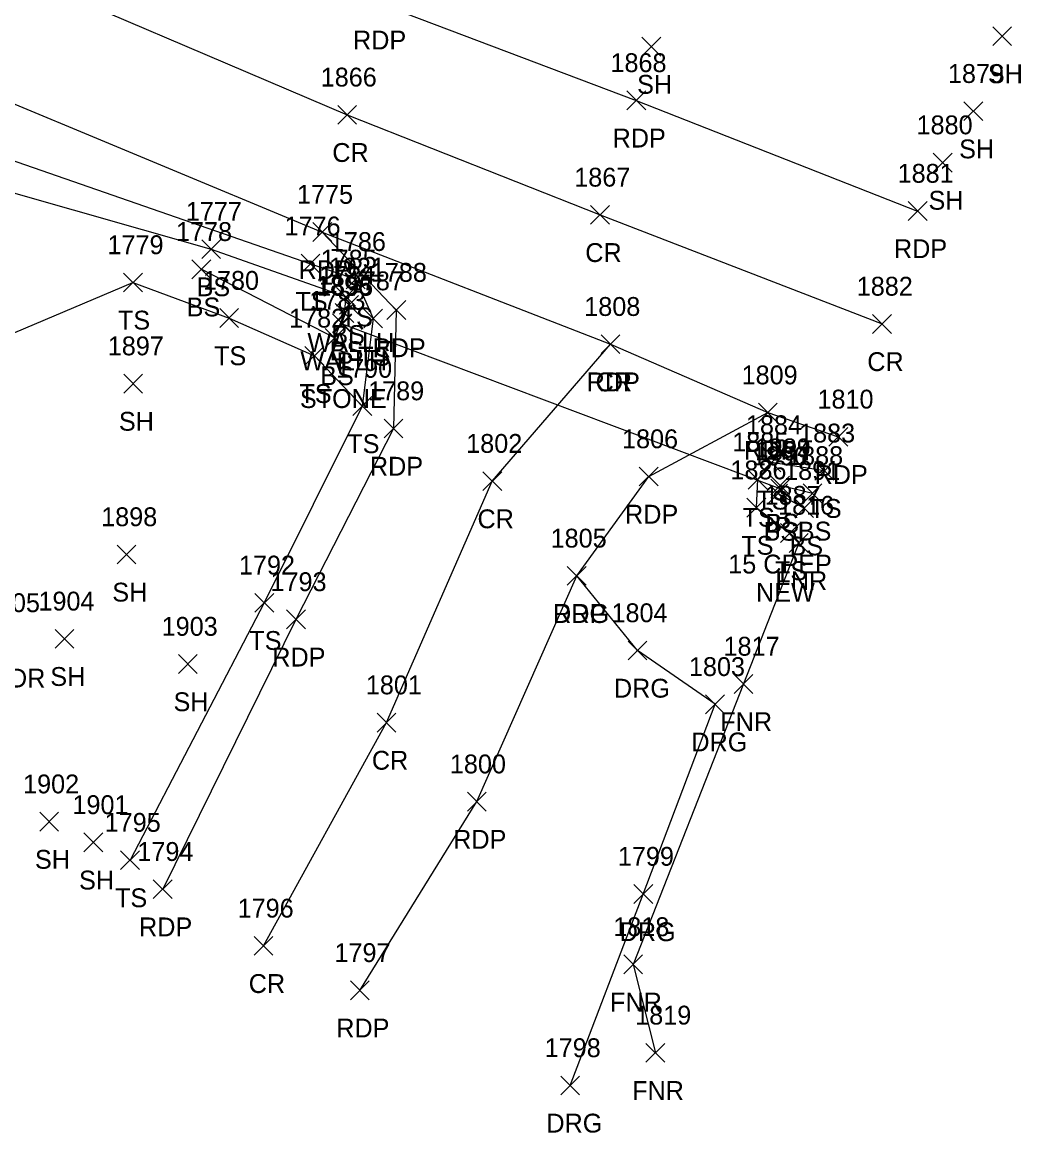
# Model space of a CAD drawing. Extents: x 1586965 to 1590952, y 716317 to 720029.
# Drawn here: x 1588133.2 to 1588239.2, y 719561.4 to 719679.3 of the extents above; entities that cross this region are included whole.
import ezdxf

# ---------------------------------------------------------------- set-up
doc = ezdxf.new("R2010")
doc.units = 0
for name, color, linetype in [('D_A', 7, 'Continuous'), ('D_C', 7, 'Continuous'), ('D_I', 7, 'Continuous'), ('D_TIC', 7, 'Continuous'), ('DCP', 7, 'Continuous'), ('DHW', 7, 'Continuous'), ('L_A', 7, 'Continuous'), ('L_I', 7, 'Continuous'), ('L_TIC', 7, 'Continuous'), ('LELB', 7, 'Continuous'), ('LFNC', 7, 'Continuous'), ('P_A', 7, 'Continuous'), ('P_I', 7, 'Continuous'), ('P_TIC', 7, 'Continuous'), ('PET', 7, 'Continuous'), ('PRC', 7, 'Continuous'), ('R_A', 7, 'Continuous'), ('R_I', 7, 'Continuous'), ('R_TIC', 7, 'Continuous'), ('RDG', 7, 'Continuous')]:
    doc.layers.add(name, color=color, linetype=linetype)

msp = doc.modelspace()

# ---------------------------------------------------------------- linework, layer by layer
at = {"layer": 'D_TIC'}
for points in [[(1588166.93, 719648.29), (1588168.93, 719650.29)], [(1588168.93, 719648.29), (1588166.93, 719650.29)], [(1588166.18, 719646.35), (1588168.18, 719648.35)], [(1588168.18, 719646.35), (1588166.18, 719648.35)], [(1588166.24, 719646.26), (1588168.24, 719648.26)], [(1588168.24, 719646.26), (1588166.24, 719648.26)], [(1588212.71, 719628.79), (1588214.71, 719630.79)], [(1588214.71, 719628.79), (1588212.71, 719630.79)]]:
    msp.add_lwpolyline(points, dxfattribs=at)
at = {"layer": 'DCP'}
msp.add_lwpolyline([(1588213.71, 719629.79), (1588167.24, 719647.26)], dxfattribs=at)
at = {"layer": 'DHW'}
msp.add_lwpolyline([(1588167.18, 719647.35), (1588167.93, 719649.29)], dxfattribs=at)
at = {"layer": 'L_TIC'}
for points in [[(1588236.25, 719676.81), (1588238.25, 719678.81)], [(1588238.25, 719676.81), (1588236.25, 719678.81)], [(1588199.02, 719675.69), (1588201.02, 719677.69)], [(1588201.02, 719675.69), (1588199.02, 719677.69)], [(1588233.2, 719668.84), (1588235.2, 719670.84)], [(1588235.2, 719668.84), (1588233.2, 719670.84)], [(1588229.95, 719663.39), (1588231.95, 719665.39)], [(1588231.95, 719663.39), (1588229.95, 719665.39)], [(1588152.31, 719654.21), (1588154.31, 719656.21)], [(1588154.31, 719654.21), (1588152.31, 719656.21)], [(1588162.84, 719652.66), (1588164.84, 719654.66)], [(1588164.84, 719652.66), (1588162.84, 719654.66)], [(1588151.26, 719652.07), (1588153.26, 719654.07)], [(1588153.26, 719652.07), (1588151.26, 719654.07)], [(1588144, 719650.67), (1588146, 719652.67)], [(1588146, 719650.67), (1588144, 719652.67)], [(1588167.64, 719651.01), (1588169.64, 719653.01)], [(1588169.64, 719651.01), (1588167.64, 719653.01)], [(1588166.62, 719649.14), (1588168.62, 719651.14)], [(1588168.62, 719649.14), (1588166.62, 719651.14)], [(1588166.62, 719649.14), (1588168.62, 719651.14)], [(1588168.62, 719649.14), (1588166.62, 719651.14)], [(1588154.21, 719646.89), (1588156.21, 719648.89)], [(1588156.21, 719646.89), (1588154.21, 719648.89)], [(1588166.45, 719647.42), (1588168.45, 719649.42)], [(1588168.45, 719647.42), (1588166.45, 719649.42)], [(1588169.5, 719646.84), (1588171.5, 719648.84)], [(1588171.5, 719646.84), (1588169.5, 719648.84)], [(1588165.42, 719644.78), (1588167.42, 719646.78)], [(1588167.42, 719644.78), (1588165.42, 719646.78)], [(1588163.26, 719642.88), (1588165.26, 719644.88)], [(1588165.26, 719642.88), (1588163.26, 719644.88)], [(1588144.02, 719639.94), (1588146.02, 719641.94)], [(1588146.02, 719639.94), (1588144.02, 719641.94)], [(1588168.34, 719637.56), (1588170.34, 719639.56)], [(1588170.34, 719637.56), (1588168.34, 719639.56)], [(1588168.34, 719637.56), (1588170.34, 719639.56)], [(1588170.34, 719637.56), (1588168.34, 719639.56)], [(1588211.76, 719631.57), (1588213.76, 719633.57)], [(1588213.76, 719631.57), (1588211.76, 719633.57)], [(1588217.39, 719630.69), (1588219.39, 719632.69)], [(1588219.39, 719630.69), (1588217.39, 719632.69)], [(1588210.3, 719629.75), (1588212.3, 719631.75)], [(1588212.3, 719629.75), (1588210.3, 719631.75)], [(1588212.69, 719629.12), (1588214.69, 719631.12)], [(1588214.69, 719629.12), (1588212.69, 719631.12)], [(1588212.48, 719628.27), (1588214.48, 719630.27)], [(1588214.48, 719628.27), (1588212.48, 719630.27)], [(1588216.12, 719628.29), (1588218.12, 719630.29)], [(1588218.12, 719628.29), (1588216.12, 719630.29)], [(1588210.16, 719626.78), (1588212.16, 719628.78)], [(1588212.16, 719626.78), (1588210.16, 719628.78)], [(1588215.24, 719626.72), (1588217.24, 719628.72)], [(1588217.24, 719626.72), (1588215.24, 719628.72)], [(1588213.73, 719624.08), (1588215.73, 719626.08)], [(1588215.73, 719624.08), (1588213.73, 719626.08)], [(1588214.66, 719623.03), (1588216.66, 719625.03)], [(1588216.66, 719623.03), (1588214.66, 719625.03)], [(1588143.32, 719621.81), (1588145.32, 719623.81)], [(1588145.32, 719621.81), (1588143.32, 719623.81)], [(1588157.94, 719616.68), (1588159.94, 719618.68)], [(1588159.94, 719616.68), (1588157.94, 719618.68)], [(1588136.74, 719612.86), (1588138.74, 719614.86)], [(1588138.74, 719612.86), (1588136.74, 719614.86)], [(1588149.82, 719610.18), (1588151.82, 719612.18)], [(1588151.82, 719610.18), (1588149.82, 719612.18)], [(1588208.81, 719608.07), (1588210.81, 719610.07)], [(1588210.81, 719608.07), (1588208.81, 719610.07)], [(1588135.11, 719593.46), (1588137.11, 719595.46)], [(1588137.11, 719593.46), (1588135.11, 719595.46)], [(1588139.79, 719591.26), (1588141.79, 719593.26)], [(1588141.79, 719591.26), (1588139.79, 719593.26)], [(1588143.69, 719589.38), (1588145.69, 719591.38)], [(1588145.69, 719589.38), (1588143.69, 719591.38)], [(1588197.1, 719578.31), (1588199.1, 719580.31)], [(1588199.1, 719578.31), (1588197.1, 719580.31)], [(1588199.45, 719568.93), (1588201.45, 719570.93)], [(1588201.45, 719568.93), (1588199.45, 719570.93)]]:
    msp.add_lwpolyline(points, dxfattribs=at)
at = {"layer": 'LELB'}
for points in [[(1587769.54, 719828.25), (1587817.81, 719818.92), (1587845.39, 719810.87), (1587866.59, 719802.16), (1587894.5, 719791.41), (1587924.64, 719774.45), (1587960.66, 719756.07), (1587994.24, 719738.05), (1588029.81, 719715.93), (1588049.13, 719705.79), (1588061.35, 719699.86), (1588090.7, 719682.25), (1588125.12, 719667.08), (1588163.84, 719653.66), (1588168.64, 719652.01), (1588170.5, 719647.84), (1588169.34, 719638.56), (1588158.94, 719617.68), (1588144.69, 719590.38)], [(1587769.54, 719828.25), (1587817.81, 719818.92), (1587845.39, 719810.87), (1587866.59, 719802.16), (1587894.5, 719791.41), (1587924.64, 719774.45), (1587960.66, 719756.07), (1587994.24, 719738.05), (1588029.81, 719715.93), (1588049.13, 719705.79), (1588061.35, 719699.86), (1588090.7, 719682.25), (1588125.12, 719667.08), (1588163.84, 719653.66), (1588168.64, 719652.01), (1588170.5, 719647.84), (1588169.34, 719638.56), (1588158.94, 719617.68), (1588144.69, 719590.38)], [(1587893.61, 719788.22), (1587923.32, 719772.46), (1587959.45, 719753.99), (1587990.31, 719736.86), (1587992.49, 719736.59), (1587993.47, 719735.49), (1587996.7, 719733.15), (1588001.37, 719729.89), (1588028.07, 719713.52), (1588047.21, 719701.72), (1588059.27, 719695.66), (1588101.54, 719672.79), (1588123.97, 719663.55), (1588153.31, 719655.21), (1588167.62, 719650.14)], [(1587893.61, 719788.22), (1587923.32, 719772.46), (1587959.45, 719753.99), (1587990.31, 719736.86), (1587992.49, 719736.59), (1587993.47, 719735.49), (1587996.7, 719733.15), (1588001.37, 719729.89), (1588028.07, 719713.52), (1588047.21, 719701.72), (1588059.27, 719695.66), (1588101.54, 719672.79), (1588123.97, 719663.55), (1588153.31, 719655.21), (1588167.62, 719650.14)], [(1588058.86, 719666.98), (1588078.17, 719656.22), (1588092.4, 719646.28), (1588110.25, 719653.63), (1588128.24, 719644.6), (1588145, 719651.67), (1588155.21, 719647.89), (1588164.26, 719643.88), (1588169.34, 719638.56)], [(1588058.86, 719666.98), (1588078.17, 719656.22), (1588092.4, 719646.28), (1588110.25, 719653.63), (1588128.24, 719644.6), (1588145, 719651.67), (1588155.21, 719647.89), (1588164.26, 719643.88), (1588169.34, 719638.56)], [(1588152.26, 719653.07), (1588166.42, 719645.78), (1588167.45, 719648.42), (1588167.62, 719650.14)], [(1588152.26, 719653.07), (1588166.42, 719645.78), (1588167.45, 719648.42), (1588167.62, 719650.14)], [(1588218.39, 719631.69), (1588212.76, 719632.57), (1588211.3, 719630.75), (1588211.16, 719627.78), (1588214.73, 719625.08)], [(1588218.39, 719631.69), (1588212.76, 719632.57), (1588211.3, 719630.75), (1588211.16, 719627.78), (1588214.73, 719625.08)], [(1588217.12, 719629.29), (1588213.69, 719630.12), (1588213.48, 719629.27), (1588216.24, 719627.72)], [(1588217.12, 719629.29), (1588213.69, 719630.12), (1588213.48, 719629.27), (1588216.24, 719627.72)]]:
    msp.add_lwpolyline(points, dxfattribs=at)
at = {"layer": 'LFNC'}
msp.add_lwpolyline([(1588215.66, 719624.03), (1588209.81, 719609.07), (1588198.1, 719579.31), (1588200.45, 719569.93)], dxfattribs=at)
at = {"layer": 'P_TIC'}
for points in [[(1588197.42, 719669.99), (1588199.42, 719671.99)], [(1588199.42, 719669.99), (1588197.42, 719671.99)], [(1588166.73, 719668.46), (1588168.73, 719670.46)], [(1588168.73, 719668.46), (1588166.73, 719670.46)], [(1588193.58, 719657.84), (1588195.58, 719659.84)], [(1588195.58, 719657.84), (1588193.58, 719659.84)], [(1588227.28, 719658.25), (1588229.28, 719660.25)], [(1588229.28, 719658.25), (1588227.28, 719660.25)], [(1588164.1, 719656.02), (1588166.1, 719658.02)], [(1588166.1, 719656.02), (1588164.1, 719658.02)], [(1588164.1, 719656.02), (1588166.1, 719658.02)], [(1588166.1, 719656.02), (1588164.1, 719658.02)], [(1588171.95, 719647.74), (1588173.95, 719649.74)], [(1588173.95, 719647.74), (1588171.95, 719649.74)], [(1588223.51, 719646.27), (1588225.51, 719648.27)], [(1588225.51, 719646.27), (1588223.51, 719648.27)], [(1588194.68, 719644.12), (1588196.68, 719646.12)], [(1588196.68, 719644.12), (1588194.68, 719646.12)], [(1588194.68, 719644.12), (1588196.68, 719646.12)], [(1588196.68, 719644.12), (1588194.68, 719646.12)], [(1588211.38, 719636.86), (1588213.38, 719638.86)], [(1588213.38, 719636.86), (1588211.38, 719638.86)], [(1588211.38, 719636.86), (1588213.38, 719638.86)], [(1588213.38, 719636.86), (1588211.38, 719638.86)], [(1588171.66, 719635.17), (1588173.66, 719637.17)], [(1588173.66, 719635.17), (1588171.66, 719637.17)], [(1588218.86, 719634.29), (1588220.86, 719636.29)], [(1588220.86, 719634.29), (1588218.86, 719636.29)], [(1588182.14, 719629.59), (1588184.14, 719631.59)], [(1588184.14, 719629.59), (1588182.14, 719631.59)], [(1588198.74, 719630.08), (1588200.74, 719632.08)], [(1588200.74, 719630.08), (1588198.74, 719632.08)], [(1588191.1, 719619.54), (1588193.1, 719621.54)], [(1588193.1, 719619.54), (1588191.1, 719621.54)], [(1588161.3, 719614.92), (1588163.3, 719616.92)], [(1588163.3, 719614.92), (1588161.3, 719616.92)], [(1588170.92, 719603.97), (1588172.92, 719605.97)], [(1588172.92, 719603.97), (1588170.92, 719605.97)], [(1588180.5, 719595.58), (1588182.5, 719597.58)], [(1588182.5, 719595.58), (1588180.5, 719597.58)], [(1588147.16, 719586.29), (1588149.16, 719588.29)], [(1588149.16, 719586.29), (1588147.16, 719588.29)], [(1588157.86, 719580.28), (1588159.86, 719582.28)], [(1588159.86, 719580.28), (1588157.86, 719582.28)], [(1588168.09, 719575.56), (1588170.09, 719577.56)], [(1588170.09, 719575.56), (1588168.09, 719577.56)]]:
    msp.add_lwpolyline(points, dxfattribs=at)
at = {"layer": 'PET'}
for points in [[(1587795.98, 719858.74), (1587820.3, 719853.13), (1587857.37, 719841.42), (1587877.69, 719833.83), (1587907.04, 719819.84), (1587939.32, 719802.03), (1587973.69, 719783.16), (1588008.21, 719763.34), (1588019.61, 719757.58), (1588045.18, 719744.38), (1588072.84, 719731.02), (1588081.8, 719723.85), (1588104.43, 719712.22), (1588133.68, 719697.26), (1588170.87, 719681.39), (1588198.42, 719670.99), (1588228.28, 719659.25)], [(1587769.59, 719834.05), (1587819.16, 719826.14), (1587848.36, 719816.77), (1587868.73, 719807.9), (1587895.82, 719795.75), (1587926.99, 719779.02), (1587962.24, 719759.15), (1587995.65, 719740.56), (1588031.83, 719719.54), (1588060.89, 719703.68), (1588093.53, 719688.06), (1588127.35, 719672.7), (1588165.1, 719657.02), (1588195.68, 719645.12), (1588212.38, 719637.86), (1588219.86, 719635.29)], [(1588165.1, 719657.02), (1588172.95, 719648.74), (1588172.66, 719636.17), (1588162.3, 719615.92), (1588148.16, 719587.29)], [(1588169.09, 719576.56), (1588181.5, 719596.58), (1588192.1, 719620.54), (1588199.74, 719631.08), (1588212.38, 719637.86)]]:
    msp.add_lwpolyline(points, dxfattribs=at)
at = {"layer": 'PRC'}
for points in [[(1587770.57, 719846.88), (1587822.37, 719838.71), (1587852.49, 719828.95), (1587873.58, 719820.04), (1587901.35, 719807.55), (1587933.49, 719790.19), (1587967.95, 719771.53), (1588001.84, 719751.71), (1588038.72, 719731.7), (1588068.79, 719715.56), (1588099.02, 719700.65), (1588127.2, 719686.75), (1588167.73, 719669.46), (1588194.58, 719658.84), (1588224.51, 719647.27)], [(1587770.57, 719846.88), (1587822.37, 719838.71), (1587852.49, 719828.95), (1587873.58, 719820.04), (1587901.35, 719807.55), (1587933.49, 719790.19), (1587967.95, 719771.53), (1588001.84, 719751.71), (1588038.72, 719731.7), (1588068.79, 719715.56), (1588099.02, 719700.65), (1588127.2, 719686.75), (1588167.73, 719669.46), (1588194.58, 719658.84), (1588224.51, 719647.27)], [(1588158.86, 719581.28), (1588171.92, 719604.97), (1588183.14, 719630.59), (1588195.68, 719645.12)], [(1588158.86, 719581.28), (1588171.92, 719604.97), (1588183.14, 719630.59), (1588195.68, 719645.12)]]:
    msp.add_lwpolyline(points, dxfattribs=at)
at = {"layer": 'R_TIC'}
for points in [[(1588191.1, 719619.54), (1588193.1, 719621.54)], [(1588193.1, 719619.54), (1588191.1, 719621.54)], [(1588197.56, 719611.62), (1588199.56, 719613.62)], [(1588199.56, 719611.62), (1588197.56, 719613.62)], [(1588205.78, 719605.91), (1588207.78, 719607.91)], [(1588207.78, 719605.91), (1588205.78, 719607.91)], [(1588198.17, 719585.78), (1588200.17, 719587.78)], [(1588200.17, 719585.78), (1588198.17, 719587.78)], [(1588190.4, 719565.47), (1588192.4, 719567.47)], [(1588192.4, 719565.47), (1588190.4, 719567.47)]]:
    msp.add_lwpolyline(points, dxfattribs=at)
at = {"layer": 'RDG'}
msp.add_lwpolyline([(1588191.4, 719566.47), (1588199.17, 719586.78), (1588206.78, 719606.91), (1588198.56, 719612.62), (1588192.1, 719620.54)], dxfattribs=at)

# ---------------------------------------------------------------- texts
at = {"layer": 'D_A'}
for s, p in [('WALLH', (1588163.52, 719644.29)), ('WALLH', (1588162.77, 719642.35)), ('P', (1588166.62, 719642.26)), ('P', (1588213.09, 719624.79))]:
    msp.add_text(s, height=2, dxfattribs=at).set_placement(p)
at = {"layer": 'D_C'}
for s, p in [('STONE', (1588162.72, 719638.35)), ('15 CPEP', (1588208.18, 719620.79)), ('NEW', (1588211.13, 719617.79))]:
    msp.add_text(s, height=2, dxfattribs=at).set_placement(p)
at = {"layer": 'D_I'}
for s, p in [('1921', (1588165.8, 719652.29)), ('1896', (1588164.43, 719650.35)), ('1895', (1588164.55, 719650.26)), ('1894', (1588211.02, 719632.79))]:
    msp.add_text(s, height=2, dxfattribs=at).set_placement(p)
at = {"layer": 'L_A'}
for s, p in [('SH', (1588235.74, 719672.81)), ('SH', (1588198.51, 719671.69)), ('SH', (1588232.69, 719664.84)), ('SH', (1588229.44, 719659.39)), ('BS', (1588151.75, 719650.21)), ('BS', (1588150.7, 719648.07)), ('TS', (1588162.25, 719648.66)), ('TS', (1588143.41, 719646.67)), ('TS', (1588167.05, 719647.01)), ('BS', (1588166.06, 719645.14)), ('BS', (1588166.06, 719645.14)), ('BS', (1588165.89, 719643.42)), ('TS', (1588153.61, 719642.89)), ('TS', (1588168.91, 719642.84)), ('BS', (1588164.87, 719640.78)), ('TS', (1588162.67, 719638.88)), ('SH', (1588143.51, 719635.94)), ('TS', (1588167.75, 719633.56)), ('TS', (1588167.75, 719633.56)), ('TS', (1588211.17, 719627.57)), ('TS', (1588216.8, 719626.69)), ('TS', (1588209.71, 719625.75)), ('BS', (1588211.93, 719624.27)), ('BS', (1588212.13, 719625.12)), ('BS', (1588215.56, 719624.29)), ('TS', (1588209.57, 719622.78)), ('BS', (1588214.68, 719622.72)), ('TS', (1588213.14, 719620.08)), ('FNR', (1588213.19, 719619.03)), ('SH', (1588142.81, 719617.81)), ('TS', (1588157.35, 719612.68)), ('WDR', (1588129.32, 719608.69)), ('SH', (1588136.23, 719608.86)), ('SH', (1588149.31, 719606.18)), ('FNR', (1588207.34, 719604.07)), ('SH', (1588134.6, 719589.46)), ('SH', (1588139.28, 719587.26)), ('TS', (1588143.1, 719585.38)), ('FNR', (1588195.64, 719574.31)), ('FNR', (1588197.98, 719564.93))]:
    msp.add_text(s, height=2, dxfattribs=at).set_placement(p)
at = {"layer": 'L_I'}
for s, p in [('1879', (1588231.5, 719672.84)), ('1880', (1588228.17, 719667.39)), ('1777', (1588150.61, 719658.21)), ('1778', (1588149.57, 719656.07)), ('1776', (1588161.09, 719656.66)), ('1786', (1588165.9, 719655.01)), ('1779', (1588142.3, 719654.67)), ('1785', (1588164.92, 719653.14)), ('1785', (1588164.92, 719653.14)), ('1784', (1588164.76, 719651.42)), ('1780', (1588152.43, 719650.89)), ('1787', (1588167.81, 719650.84)), ('1783', (1588163.73, 719648.78)), ('1782', (1588161.57, 719646.88)), ('1897', (1588142.33, 719643.94)), ('1790', (1588166.56, 719641.56)), ('1790', (1588166.56, 719641.56)), ('1884', (1588210.06, 719635.57)), ('1885', (1588208.61, 719633.75)), ('1883', (1588215.7, 719634.69)), ('1889', (1588210.99, 719633.12)), ('1890', (1588210.7, 719632.27)), ('1888', (1588214.43, 719632.29)), ('1886', (1588208.41, 719630.78)), ('1891', (1588214.11, 719630.72)), ('1887', (1588212.04, 719628.08)), ('1816', (1588213.47, 719627.03)), ('1898', (1588141.63, 719625.81)), ('1792', (1588156.25, 719620.68)), ('1905', (1588129.18, 719616.69)), ('1904', (1588134.97, 719616.86)), ('1903', (1588148.05, 719614.18)), ('1817', (1588207.68, 719612.07)), ('1902', (1588133.34, 719597.46)), ('1901', (1588138.58, 719595.26)), ('1795', (1588142, 719593.38)), ('1818', (1588195.98, 719582.31)), ('1819', (1588198.31, 719572.93))]:
    msp.add_text(s, height=2, dxfattribs=at).set_placement(p)
at = {"layer": 'P_A'}
for s, p in [('RDP', (1588168.36, 719676.39)), ('RDP', (1588195.91, 719665.99)), ('CR', (1588166.16, 719664.46)), ('CR', (1588193.01, 719653.84)), ('RDP', (1588225.77, 719654.25)), ('RDP', (1588162.59, 719652.02)), ('RDP', (1588162.59, 719652.02)), ('RDP', (1588170.43, 719643.74)), ('CR', (1588222.94, 719642.27)), ('RDP', (1588193.16, 719640.12)), ('CR', (1588194.11, 719640.12)), ('RDP', (1588209.86, 719632.86)), ('RDP', (1588209.86, 719632.86)), ('RDP', (1588170.15, 719631.17)), ('RDP', (1588217.35, 719630.29)), ('CR', (1588181.57, 719625.59)), ('RDP', (1588197.23, 719626.08)), ('RDP', (1588189.59, 719615.54)), ('RDP', (1588159.79, 719610.92)), ('CR', (1588170.36, 719599.97)), ('RDP', (1588178.99, 719591.58)), ('RDP', (1588145.65, 719582.29)), ('CR', (1588157.29, 719576.28)), ('RDP', (1588166.58, 719571.56))]:
    msp.add_text(s, height=2, dxfattribs=at).set_placement(p)
at = {"layer": 'P_I'}
for s, p in [('1868', (1588195.68, 719673.99)), ('1866', (1588164.93, 719672.46)), ('1881', (1588226.16, 719662.25)), ('1867', (1588191.84, 719661.84)), ('1775', (1588162.41, 719660.02)), ('1775', (1588162.41, 719660.02)), ('1788', (1588170.25, 719651.74)), ('1882', (1588221.82, 719650.27)), ('1808', (1588192.9, 719648.12)), ('1808', (1588192.9, 719648.12)), ('1809', (1588209.6, 719640.86)), ('1809', (1588209.6, 719640.86)), ('1789', (1588169.96, 719639.17)), ('1810', (1588217.65, 719638.29)), ('1806', (1588196.91, 719634.08)), ('1802', (1588180.37, 719633.59)), ('1805', (1588189.33, 719623.54)), ('1793', (1588159.6, 719618.92)), ('1801', (1588169.72, 719607.97)), ('1800', (1588178.64, 719599.58)), ('1794', (1588145.47, 719590.29)), ('1796', (1588156.11, 719584.28)), ('1797', (1588166.39, 719579.56))]:
    msp.add_text(s, height=2, dxfattribs=at).set_placement(p)
at = {"layer": 'R_A'}
for p in [(1588189.59, 719615.54), (1588196.05, 719607.62), (1588204.27, 719601.91), (1588196.66, 719581.78), (1588188.88, 719561.47)]:
    msp.add_text('DRG', height=2, dxfattribs=at).set_placement(p)
at = {"layer": 'R_I'}
for s, p in [('1805', (1588189.33, 719623.54)), ('1804', (1588195.79, 719615.62)), ('1803', (1588204.01, 719609.91)), ('1799', (1588196.47, 719589.78)), ('1798', (1588188.7, 719569.47))]:
    msp.add_text(s, height=2, dxfattribs=at).set_placement(p)

doc.saveas('drawing.dxf')
